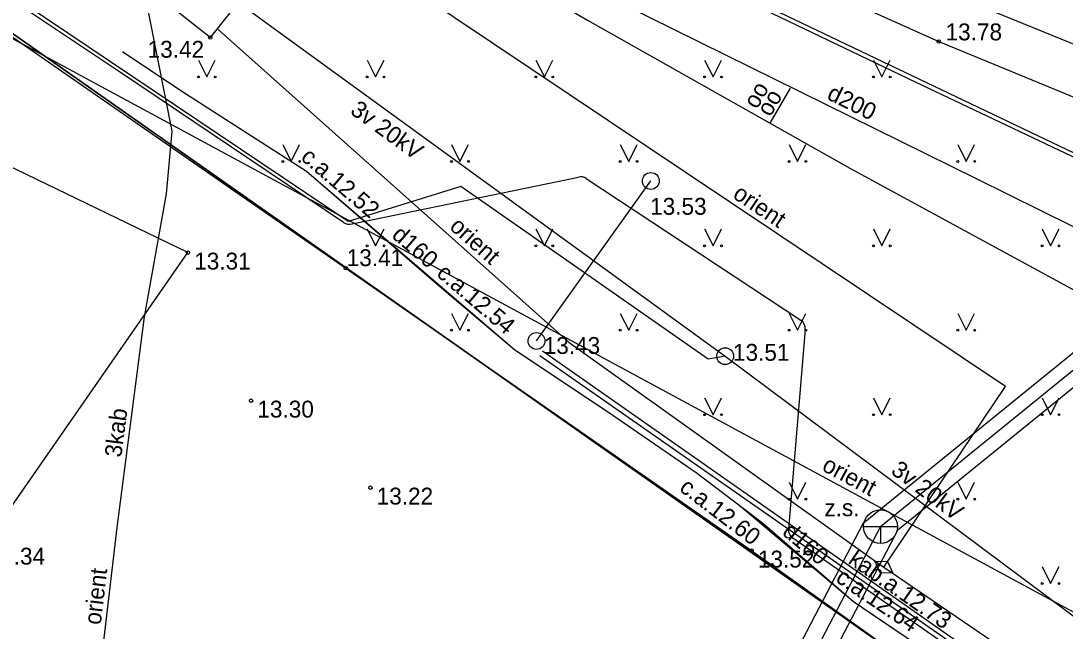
# Model space of a CAD drawing. Extents: x 503904 to 504094, y 304688 to 304960.
# Drawn here: x 503996.99 to 504027.93, y 304866.09 to 304884.16 of the extents above; entities that cross this region are included whole.
import ezdxf

# ---------------------------------------------------------------- set-up
doc = ezdxf.new("R2010")
doc.units = 0
for name, color, linetype in [('APGR_SARK_####_####_#', 7, 'Continuous'), ('APGS_VADP_ZSPR_####_#', 7, 'Continuous'), ('CELI_CAPM_####_####_#', 7, 'Continuous'), ('CELI_CMAL_####_####_#', 7, 'Continuous'), ('ELEK_ACRL_####_####_#', 7, 'Continuous'), ('ELEK_ACRL_####_TKST_#', 7, 'Continuous'), ('ELEK_ELEM_####_####_#', 7, 'Continuous'), ('ELEK_SAVL_####_####_#', 7, 'Continuous'), ('ELEK_STTP_####_####_#', 7, 'Continuous'), ('ELEK_VADP_NEDR_####_#', 7, 'Continuous'), ('ELEK_VADP_VSPR_####_#', 7, 'Continuous'), ('ELEK_VADP_VSPR_####_I', 7, 'Continuous'), ('ELEK_VADP_VSPR_TKST_#', 7, 'Continuous'), ('ELEK_VADP_ZSPR_####_#', 7, 'Continuous'), ('ELEK_VADP_ZSPR_TKST_#', 7, 'Continuous'), ('ELEK_VADV_VSPR_####_#', 7, 'Continuous'), ('ELEK_VADV_VSPR_TKST_#', 7, 'Continuous'), ('GAZE_VADP_VSP2_####_#', 7, 'Continuous'), ('GAZE_VADP_VSP2_TKST_#', 7, 'Continuous'), ('NORB_ZOGS_ZSTP_####_#', 7, 'Continuous'), ('RELJ_AATZ_####_TKST_#', 7, 'Continuous'), ('RELJ_ELEM_####_####_#', 7, 'Continuous'), ('ROBZ_UZMR_####_####_#', 7, 'Continuous'), ('SAKK_IZVK_####_TKST_#', 7, 'Continuous'), ('SAKK_KKAN_####_####_#', 7, 'Continuous'), ('SILT_ELEM_####_####_#', 7, 'Continuous'), ('SILT_ELEM_####_TKST_#', 7, 'Continuous'), ('SILT_VADP_NEDR_####_#', 7, 'Continuous'), ('SILT_VADP_UDEN_TKAM_#', 7, 'Continuous'), ('TERT_ELEM_####_####_#', 7, 'Continuous'), ('UDTK_VADP_UDEN_####_#', 7, 'Continuous'), ('UDTK_VADP_UDEN_TKST_#', 7, 'Continuous')]:
    doc.layers.add(name, color=color, linetype=linetype)

msp = doc.modelspace()

# ---------------------------------------------------------------- linework, layer by layer
at = {"layer": 'APGR_SARK_####_####_#'}
msp.add_line((503981.123, 304894.75), (504030.463, 304860.121), dxfattribs=at)
at = {"layer": 'APGS_VADP_ZSPR_####_#'}
for points in [[(504034.948, 304837.203), (504032.464, 304838.354), (504032.46, 304838.624), (504032.497, 304838.963), (504034.767, 304843.029), (504037.037, 304847.095), (504041.785, 304855.598), (504046.532, 304864.101), (504046.909, 304866.055), (504048.051, 304868.025), (504049.192, 304869.995), (504049.205, 304870.202), (504049.157, 304870.343), (504042.295, 304873.577), (504035.433, 304876.812), (504031.898, 304878.478), (504020.359, 304883.989), (504008.82, 304889.499), (504008.617, 304889.54), (504008.431, 304889.443), (504006.058, 304885.968)], [(504006.081, 304886.016), (504006.524, 304886.457), (504007.485, 304887.87), (504008.446, 304889.284), (504008.616, 304889.405), (504008.824, 304889.386), (504016.168, 304885.866), (504023.512, 304882.345), (504029.465, 304879.528), (504035.491, 304876.677), (504037.943, 304875.532), (504038.212, 304875.634), (504038.416, 304876.08), (504038.226, 304875.558), (504038.331, 304875.343), (504039.638, 304874.712), (504041.796, 304873.674), (504045.914, 304871.662), (504049.181, 304870.056), (504051.511, 304869.798), (504052.144, 304869.735)]]:
    msp.add_lwpolyline(points, dxfattribs=at)
at = {"layer": 'CELI_CAPM_####_####_#'}
msp.add_lwpolyline([(504042.469, 304879.012), (504039.999, 304879.481), (504033.709, 304881.219), (504024.994, 304884.76), (504014.798, 304889.372), (504004.157, 304894.141)], dxfattribs=at)
at = {"layer": 'CELI_CMAL_####_####_#'}
for points in [[(504004.157, 304894.141), (504003.635, 304892.793), (504014.253, 304888.009), (504024.188, 304883.551), (504033.132, 304879.868), (504039.457, 304878.088), (504042.126, 304877.631), (504042.469, 304879.012)], [(503995.849, 304868.561), (504001.94, 304877.298), (503991.776, 304882.213)]]:
    msp.add_lwpolyline(points, dxfattribs=at)
at = {"layer": 'ELEK_ACRL_####_####_#'}
for points in [[(504005.45, 304879.71), (504011.63, 304874.42), (504013.934, 304872.881)], [(504018.311, 304869.793), (504021.66, 304866.97), (504022.954, 304866.094)]]:
    msp.add_lwpolyline(points, dxfattribs=at)
at = {"layer": 'ELEK_ELEM_####_####_#'}
msp.add_lwpolyline([(504022.295, 304868.163), (504022.672, 304868.148), (504022.823, 304867.803), (504022.446, 304867.818)], close=True, dxfattribs=at)
for centre in [(504015.657, 304879.421), (504012.268, 304874.683), (504017.859, 304874.234)]:
    msp.add_circle(centre, 0.25, dxfattribs=at)
at = {"layer": 'ELEK_SAVL_####_####_#'}
msp.add_line((504012.268, 304874.683), (504015.657, 304879.421), dxfattribs=at)
at = {"layer": 'ELEK_STTP_####_####_#'}
msp.add_lwpolyline([(504002.404, 304886.982), (504004.147, 304885.62), (504002.601, 304883.668), (504000.867, 304885.041)], dxfattribs=at)
at = {"layer": 'ELEK_VADP_NEDR_####_#'}
for points in [[(504021.775, 304819.315), (504017.104, 304821.576), (504012.433, 304823.836), (504012.326, 304823.953), (504012.339, 304824.112), (504013.491, 304826.283), (504014.644, 304828.454), (504016.196, 304831.379), (504017.749, 304834.304), (504019.433, 304837.477), (504021.118, 304840.651), (504023.847, 304845.791), (504025.258, 304848.45), (504028.54, 304854.632), (504031.821, 304860.814), (504022.135, 304867.596), (504012.45, 304874.378)], [(504012.365, 304874.256), (504022.005, 304867.531), (504031.646, 304860.805), (504025.265, 304848.775), (504019.402, 304837.719), (504017.809, 304834.715), (504016.163, 304831.611), (504014.517, 304828.507)]]:
    msp.add_lwpolyline(points, dxfattribs=at)
at = {"layer": 'ELEK_VADP_VSPR_####_#'}
for p, q in [((503999.944, 304882.63), (503993.832, 304886.735)), ((504006.549, 304878.194), (503999.944, 304882.63)), ((504006.805, 304878.156), (504013.516, 304879.538)), ((504013.742, 304879.494), (504020.098, 304875.3)), ((504020.232, 304875.025), (504019.735, 304869.116)), ((504026.897, 304863.949), (504019.862, 304868.844))]:
    msp.add_line(p, q, dxfattribs=at)
msp.add_lwpolyline([(504017.859, 304874.234), (504017.356, 304874.141), (504010.022, 304879.253), (504006.684, 304878.224), (503993.887, 304886.818), (503989.112, 304889.931), (503981.666, 304895.299)], dxfattribs=at)
for centre, start, end in [((504013.577, 304879.244), 56.5809, 101.6335), ((504006.716, 304878.443), 236.1137, 287.1377), ((504019.933, 304875.05), 355.1871, 56.5809), ((504020.033, 304869.09), 175.1871, 235.1685)]:
    msp.add_arc(centre, 0.3, start, end, dxfattribs=at)
at = {"layer": 'ELEK_VADP_VSPR_####_I'}
msp.add_lwpolyline([(504000, 304883.254), (504001.73, 304882.1), (504005.45, 304879.71), (504009.45, 304876.26), (504011.63, 304874.42), (504014.37, 304872.59), (504017, 304870.79), (504018.96, 304869.3), (504021.66, 304866.97), (504030.69, 304860.86), (504043.227, 304852.046), (504043.928, 304851.566)], dxfattribs=at)
at = {"layer": 'ELEK_VADP_ZSPR_####_#'}
for points in [[(504022.559, 304867.983), (504026.163, 304873.33), (504016.676, 304879.682), (504010.965, 304883.506), (504005.254, 304887.33), (504004.874, 304887.016), (504003.476, 304886.332), (504003.299, 304886.283)], [(504000.416, 304838.443), (503998.481, 304840.029), (503998.306, 304845.209), (503998.373, 304849.851), (503998.508, 304857.812), (503999.848, 304869.157), (504000.657, 304875.395), (504001.302, 304879.043), (504001.471, 304880.898), (504000.618, 304885.243), (504001.595, 304885.938)], [(504002.84, 304883.907), (504013.238, 304874.636), (504017.897, 304871.307), (504022.559, 304867.983), (504028.527, 304863.916), (504031.948, 304861.583), (504040.554, 304855.614), (504044.535, 304852.853)]]:
    msp.add_lwpolyline(points, dxfattribs=at)
at = {"layer": 'ELEK_VADV_VSPR_####_#'}
for p, q in [((504003.444, 304884.699), (504017.859, 304874.234)), ((504017.859, 304874.234), (504045.046, 304853.939))]:
    msp.add_line(p, q, dxfattribs=at)
at = {"layer": 'GAZE_VADP_VSP2_####_#'}
msp.add_lwpolyline([(503989.698, 304903.414), (504000, 304898.037), (504010.212, 304892.707), (504011.048, 304889.414), (504011.884, 304886.121), (504025.295, 304879.492), (504038.706, 304872.862), (504042.754, 304870.726), (504047.158, 304868.745), (504052.063, 304869.587)], dxfattribs=at)
at = {"layer": 'NORB_ZOGS_ZSTP_####_#'}
msp.add_lwpolyline([(503994.545, 304885.205), (504006.615, 304876.836), (504018.641, 304868.474), (504030.525, 304860.01), (504021.686, 304844.338), (504014.326, 304831.324)], dxfattribs=at)
at = {"layer": 'RELJ_ELEM_####_####_#'}
for centre in [(504002.601, 304883.668), (504024.188, 304883.551), (504001.94, 304877.298), (504006.615, 304876.836), (504003.812, 304872.915), (504007.347, 304870.339), (504018.641, 304868.474)]:
    msp.add_circle(centre, 0.05, dxfattribs=at)
at = {"layer": 'ROBZ_UZMR_####_####_#'}
msp.add_lwpolyline([(504052.953, 304844.812), (504048.85, 304847.4), (504030.463, 304860.121), (503981.123, 304894.75), (503968.011, 304904.031)], dxfattribs=at)
msp.add_lwpolyline([(503923.29, 304801.044), (503978.518, 304892.436), (503981.123, 304894.75), (504030.463, 304860.121), (503981.982, 304759.672)], close=True, dxfattribs=at)
at = {"layer": 'SAKK_IZVK_####_TKST_#'}
msp.add_line((504019.196, 304881.13), (504019.789, 304882.17), dxfattribs=at)
at = {"layer": 'SAKK_KKAN_####_####_#'}
msp.add_lwpolyline([(503986.316, 304899.997), (504000, 304892.196), (504013.782, 304884.178), (504021.554, 304879.802), (504033.218, 304873.459), (504039.007, 304870.064), (504043.395, 304867.859), (504047.782, 304865.655), (504048.401, 304866.822), (504050.758, 304867.21)], dxfattribs=at)
at = {"layer": 'SILT_ELEM_####_####_#'}
for p, q in [((504021.961, 304869.185), (504022.461, 304869.185)), ((504022.461, 304869.185), (504022.961, 304869.185)), ((504022.461, 304869.185), (504022.461, 304868.685))]:
    msp.add_line(p, q, dxfattribs=at)
msp.add_circle((504022.461, 304869.185), 0.5, dxfattribs=at)
at = {"layer": 'SILT_VADP_NEDR_####_#'}
msp.add_line((504022.461, 304869.185), (504005.145, 304836.134), dxfattribs=at)
msp.add_lwpolyline([(504022.461, 304869.185), (504044.321, 304886.935)], dxfattribs=at)
at = {"layer": 'SILT_VADP_UDEN_TKAM_#'}
for p, q in [((504021.948, 304869.284), (504004.702, 304836.366)), ((504022.974, 304869.086), (504005.588, 304835.902))]:
    msp.add_line(p, q, dxfattribs=at)
for points in [[(504021.948, 304869.284), (504043.838, 304887.058)], [(504022.974, 304869.086), (504044.804, 304886.812)]]:
    msp.add_lwpolyline(points, dxfattribs=at)
at = {"layer": 'TERT_ELEM_####_####_#'}
for p, q in [((504002.25, 304883), (504002.5, 304882.5)), ((504002.5, 304882.5), (504002.75, 304883)), ((504007.25, 304883), (504007.5, 304882.5)), ((504007.5, 304882.5), (504007.75, 304883)), ((504012.25, 304883), (504012.5, 304882.5)), ((504012.5, 304882.5), (504012.75, 304883)), ((504017.25, 304883), (504017.5, 304882.5)), ((504017.5, 304882.5), (504017.75, 304883)), ((504022.25, 304883), (504022.5, 304882.5)), ((504022.5, 304882.5), (504022.75, 304883)), ((504004.75, 304880.5), (504005, 304880)), ((504005, 304880), (504005.25, 304880.5)), ((504009.75, 304880.5), (504010, 304880)), ((504010, 304880), (504010.25, 304880.5)), ((504014.75, 304880.5), (504015, 304880)), ((504015, 304880), (504015.25, 304880.5)), ((504019.75, 304880.5), (504020, 304880)), ((504020, 304880), (504020.25, 304880.5)), ((504024.75, 304880.5), (504025, 304880)), ((504025, 304880), (504025.25, 304880.5)), ((504007.25, 304878), (504007.5, 304877.5)), ((504007.5, 304877.5), (504007.75, 304878)), ((504012.25, 304878), (504012.5, 304877.5)), ((504012.5, 304877.5), (504012.75, 304878)), ((504017.25, 304878), (504017.5, 304877.5)), ((504017.5, 304877.5), (504017.75, 304878)), ((504022.25, 304878), (504022.5, 304877.5)), ((504022.5, 304877.5), (504022.75, 304878)), ((504027.25, 304878), (504027.5, 304877.5)), ((504027.5, 304877.5), (504027.75, 304878)), ((504009.75, 304875.5), (504010, 304875)), ((504010, 304875), (504010.25, 304875.5)), ((504014.75, 304875.5), (504015, 304875)), ((504015, 304875), (504015.25, 304875.5)), ((504019.75, 304875.5), (504020, 304875)), ((504020, 304875), (504020.25, 304875.5)), ((504024.75, 304875.5), (504025, 304875)), ((504025, 304875), (504025.25, 304875.5)), ((504017.25, 304873), (504017.5, 304872.5)), ((504017.5, 304872.5), (504017.75, 304873)), ((504022.25, 304873), (504022.5, 304872.5)), ((504022.5, 304872.5), (504022.75, 304873)), ((504027.25, 304873), (504027.5, 304872.5)), ((504027.5, 304872.5), (504027.75, 304873)), ((504019.75, 304870.5), (504020, 304870)), ((504020, 304870), (504020.25, 304870.5)), ((504024.75, 304870.5), (504025, 304870)), ((504025, 304870), (504025.25, 304870.5)), ((504027.25, 304868), (504027.5, 304867.5)), ((504027.5, 304867.5), (504027.75, 304868))]:
    msp.add_line(p, q, dxfattribs=at)
for centre, radius in [((504002.25, 304882.5), 0.028), ((504002.75, 304882.5), 0.0263), ((504007.25, 304882.5), 0.028), ((504007.75, 304882.5), 0.0263), ((504012.25, 304882.5), 0.028), ((504012.75, 304882.5), 0.0263), ((504017.25, 304882.5), 0.028), ((504017.75, 304882.5), 0.0263), ((504022.25, 304882.5), 0.028), ((504022.75, 304882.5), 0.0263), ((504004.75, 304880), 0.028), ((504005.25, 304880), 0.0263), ((504009.75, 304880), 0.028), ((504010.25, 304880), 0.0263), ((504014.75, 304880), 0.028), ((504015.25, 304880), 0.0263), ((504019.75, 304880), 0.028), ((504020.25, 304880), 0.0263), ((504024.75, 304880), 0.028), ((504025.25, 304880), 0.0263), ((504007.25, 304877.5), 0.028), ((504007.75, 304877.5), 0.0263), ((504012.25, 304877.5), 0.028), ((504012.75, 304877.5), 0.0263), ((504017.25, 304877.5), 0.028), ((504017.75, 304877.5), 0.0263), ((504022.25, 304877.5), 0.028), ((504022.75, 304877.5), 0.0263), ((504027.25, 304877.5), 0.028), ((504027.75, 304877.5), 0.0263), ((504009.75, 304875), 0.028), ((504010.25, 304875), 0.0263), ((504014.75, 304875), 0.028), ((504015.25, 304875), 0.0263), ((504019.75, 304875), 0.028), ((504020.25, 304875), 0.0263), ((504024.75, 304875), 0.028), ((504025.25, 304875), 0.0263), ((504017.25, 304872.5), 0.028), ((504017.75, 304872.5), 0.0263), ((504022.25, 304872.5), 0.028), ((504022.75, 304872.5), 0.0263), ((504027.25, 304872.5), 0.028), ((504027.75, 304872.5), 0.0263), ((504019.75, 304870), 0.028), ((504020.25, 304870), 0.0263), ((504024.75, 304870), 0.028), ((504025.25, 304870), 0.0263), ((504027.25, 304867.5), 0.028), ((504027.75, 304867.5), 0.0263)]:
    msp.add_circle(centre, radius, dxfattribs=at)
at = {"layer": 'UDTK_VADP_UDEN_####_#'}
msp.add_lwpolyline([(504035.876, 304862.497), (503979.246, 304893.082)], dxfattribs=at)

# ---------------------------------------------------------------- texts
at = {"layer": 'ELEK_ACRL_####_TKST_#'}
for s, rotation, p in [('c.a.12.52', 319.4369, (504005.254, 304880.075)), ('d160', 319.4369, (504007.949, 304877.768)), ('c.a.12.54', 319.4369, (504009.275, 304876.633)), ('c.a.12.60', 322.7578, (504016.469, 304870.269)), ('d160', 319.8672, (504019.517, 304868.973)), ('c.a.12.64', 325.9164, (504021.099, 304867.58))]:
    msp.add_text(s, height=0.5, rotation=rotation, dxfattribs=at).set_placement(p)
at = {"layer": 'ELEK_VADP_VSPR_TKST_#'}
msp.add_text('kab.a.12.73', height=0.5, rotation=325.1695, dxfattribs=at).set_placement((504021.473, 304868.121))
at = {"layer": 'ELEK_VADP_ZSPR_TKST_#'}
for s, rotation, p in [('orient', 326.1958, (504018.051, 304878.942)), ('orient', 318.2804, (504009.662, 304878.026)), ('3kab', 82.6106, (503999.964, 304871.22)), ('orient', 83.2638, (503999.355, 304866.261))]:
    msp.add_text(s, height=0.5, rotation=rotation, dxfattribs=at).set_placement(p)
at = {"layer": 'ELEK_VADV_VSPR_TKST_#'}
for rotation, p in [(324.02, (504006.718, 304881.438)), (323.2592, (504022.738, 304870.779))]:
    msp.add_text('3v 20kV', height=0.5, rotation=rotation, dxfattribs=at).set_placement(p)
at = {"layer": 'GAZE_VADP_VSP2_TKST_#'}
msp.add_text('d200', height=0.5, rotation=333.6953, dxfattribs=at).set_placement((504020.842, 304881.86))
at = {"layer": 'RELJ_AATZ_####_TKST_#'}
for s, p in [(' 13.78', (504024.202, 304883.585)), (' 13.42', (504000.56, 304883.07)), (' 13.53', (504015.449, 304878.42)), (' 13.31', (504001.94, 304876.798)), (' 13.41', (504006.459, 304876.899)), (' 13.43', (504012.296, 304874.299)), (' 13.51', (504017.904, 304874.096)), (' 13.30', (504003.812, 304872.415)), (' 13.22', (504007.347, 304869.839)), (' 13.34', (503995.849, 304868.061)), (' 13.52', (504018.641, 304867.974))]:
    msp.add_text(s, height=0.5, dxfattribs=at).set_placement(p)
at = {"layer": 'SAKK_IZVK_####_TKST_#'}
for p in [(504018.803, 304881.525), (504019.199, 304881.298)]:
    msp.add_text('oo', height=0.5, rotation=60.3243, dxfattribs=at).set_placement(p)
at = {"layer": 'SILT_ELEM_####_TKST_#'}
msp.add_text('z.s.', height=0.5, dxfattribs=at).set_placement((504020.799, 304869.494))
at = {"layer": 'UDTK_VADP_UDEN_TKST_#'}
msp.add_text('orient', height=0.5, rotation=331.6271, dxfattribs=at).set_placement((504020.693, 304870.868))

doc.saveas('drawing.dxf')
